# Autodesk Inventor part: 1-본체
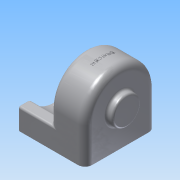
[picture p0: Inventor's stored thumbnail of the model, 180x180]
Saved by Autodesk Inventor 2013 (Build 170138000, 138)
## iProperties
Created: 2015-02
Part Number: 1-본체
Material: 알루미늄 6061
Document SubType Name: Modeling
Designer: Administrator
Density: 2.40731 g/cm^3
Mass: 559.928 g
Surface Area: 696.786 cm^2
Volume: 232.595 cm^3
Author: Administrator
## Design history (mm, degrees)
sketch "스케치1"
  geometry: L1 (25, -50)-(-25, -50); L2 (-25, -50)-(-25, 50); L3 (-25, 50)-(25, 50); L4 (25, 50)-(25, -50); L5 (25, -50)-(-25, 50); L6 (-25, -50)-(25, 50); 1 further point
  constraints: 12 end point, 2 midpoint, 2 parallel, 1 horizontal, 1 perpendicular
  dimensions: "d0" = 50 distance of L2.end L3.end; "d2" = 100 distance of L1.end L2.end
extrude "돌출1" new body sketch "스케치1" distance "d3" = 100; taper "d4" = 0 deg
fillet "모깎기1" dims "d5" = 50
sketch "스케치2"
  geometry: C1 r 25 at (50, 50); A1 r 50 centre (50, 50) between (50, 0) and (50, 100) reference; 1 further point
  constraints: 1 centre point, 1 coincident
  dimensions: "d7" = 50 diameter of C1
extrude "돌출2" join sketch "스케치2" distance "d9" = 10; taper "d10" = -20 deg
sketch "스케치3"
  geometry: C1 r 20 at (-50, 50); A1 r 50 centre (-50, 50) between (-50, 100) and (-50, 0) reference; 1 further point
  constraints: 1 centre point, 1 coincident
  dimensions: "d11" = 40 diameter of C1
extrude "돌출3" join sketch "스케치3" distance "d13" = 9; taper "d14" = 0 deg
node "작업 평면1"
sketch "스케치4"
  geometry: L1 (0, 100)-(50, 100) reference; L2 (0, 0)-(0, 100) reference; L3 (0, 0)-(50, 0) reference; L4 (0, 100)-(28, 100); L5 (30, 84.641)-(30, 100); L6 (28, 100)-(30, 100); L7 (30, 15.359)-(30, 0); L8 (0, 0)-(0, 100); L9 (30, 0)-(0, 0); A1 r 50 centre (50, 50) between (50, 0) and (50, 100) reference; A2 r 40 centre (50, 50) between (30, 84.641) and (30, 15.359); 1 further point
  constraints: 12 end point, 3 collinear, 3 point on line, 2 perpendicular, 2 point on circle, 1 centre point, 1 coincident
  dimensions: "d16" = 40 radius of A2; "d18" = 30 distance between parallel lines of L8 L5; "d19" = 30 distance between parallel lines of L2 L7
extrude "돌출4" join sketch "스케치4" stored distance "d20" = 9; taper "d21" = 0 deg
hole "구멍1" diameter "d24" = 20; stored, may be unused: countersink angle "d28" = 90 deg, drill point angle "d30" = 0 deg; dims "d25" = 6, "d26" = 28, "d27" = 10, "d29" = 14, "d38" = 10, "d39" = 10
sketch "스케치6"
  geometry: C1 r 14 at (0, 0) reference; C2 r 21.36 at (0, 0) reference; A1 r 18 centre (0, 0) between (18, 0) and (0, 18); 3 further points
  constraints: 4 point on circle, 2 horizontal alignment, 2 vertical alignment, 1 centre point, 1 coincident
  dimensions: "d40" = 36 diameter of A1
hole "구멍3" sketch "스케치6" at (18, 0), (0, 18), (-18, 0), (0, -18) diameter "d42" = 2.459; stored, may be unused: countersink angle "d46" = 90 deg, drill point angle "d48" = 118 deg; dims "d43" = 6, "d44" = 28, "d45" = 8, "d47" = 9
sketch "스케치7"
  geometry: L1 (70, 50)-(70, -50) reference; L2 (61, -41.75)-(28, -41.75); L3 (28, -41.75)-(28, 41.75); L4 (28, 41.75)-(61, 41.75); L5 (61, 41.75)-(61, -41.75); 7 further points
  constraints: 8 end point, 4 coincident, 2 midpoint, 2 parallel, 1 horizontal, 1 horizontal alignment, 1 perpendicular, 1 point on line
  dimensions: "d49" = 33 distance of L2.start L2.end; "d51" = 83.5 distance of L4.end L2.start; "d52" = 9 distance between parallel lines of L1 L5
hole "구멍4" sketch "스케치7" at (61, -41.75), (28, -41.75), (28, 41.75), (61, 41.75) diameter "d53" = 5.134; stored, may be unused: countersink angle "d57" = 90 deg, drill point angle "d59" = 118 deg; dims "d54" = 10, "d55" = 28, "d56" = 8, "d58" = 13
fillet "모깎기2" dims "d60" = 0.3
fillet "모깎기3" dims "d61" = 10
fillet "모깎기4" dims "d62" = 3
fillet "모깎기5" dims "d63" = 3
chamfer "모따기1" distance "d64" = 1; stored, may be unused: second distance "d65" = 2, angle "d66" = 45 deg
node "작업 평면2"
sketch "스케치8"
  geometry: L1 (37.5, 40)-(37.5, -40) reference; 3 further points
  constraints: 1 horizontal alignment, 1 midpoint, 1 other
  dimensions: "d67" = 25 distance from line of point (12.5, 0) L1
feature "엠보싱1" sketch "스케치8" dims "d0" = 50, "d2" = 100, "d68" = 0.5, "d69" = 0
fillet "모깎기7" dims "d71" = 3
fillet "모깎기8" dims "d72" = 3
node "작업 평면3"
sketch "스케치9"
  geometry: 1 further point
node "작업 평면5"
sketch "스케치11"
  geometry: L1 (0, 46)-(-50, 46); L2 (0, -46)-(-50, -46); L3 (-50, 47)-(-50, -47) reference; A1 r 50 centre (0, 0) between (0, -50) and (0, 50) reference; A2 r 46 centre (0, 0) between (0, -46) and (0, 46); 1 further point
  constraints: 4 end point, 2 point on circle, 2 point on line, 2 tangent, 1 centre point, 1 horizontal, 1 parallel
  dimensions: "d79" = 4 radial gap between concentric circles of A1 A2
extrude "돌출5" cut sketch "스케치11" stored distance "d80" = 42; taper "d81" = 0 deg
sketch "스케치12"
  geometry: A1 r 46 centre (0, 0) between (0, -46) and (0, 46) reference; 2 further points
  constraints: 1 coincident
hole "구멍5" sketch "스케치12" at (0, 0) diameter "d82" = 20; stored, may be unused: countersink angle "d86" = 90 deg, drill point angle "d88" = 0 deg; dims "d83" = 6, "d84" = 28, "d85" = 8, "d87" = 10
fillet "모깎기10" dims "d89" = 0.3
fillet "모깎기11" dims "d90" = 3
fillet "모깎기12" dims "d91" = 6
node "솔리드1"
other parameters: "d15" = 45, "d74" = 0
